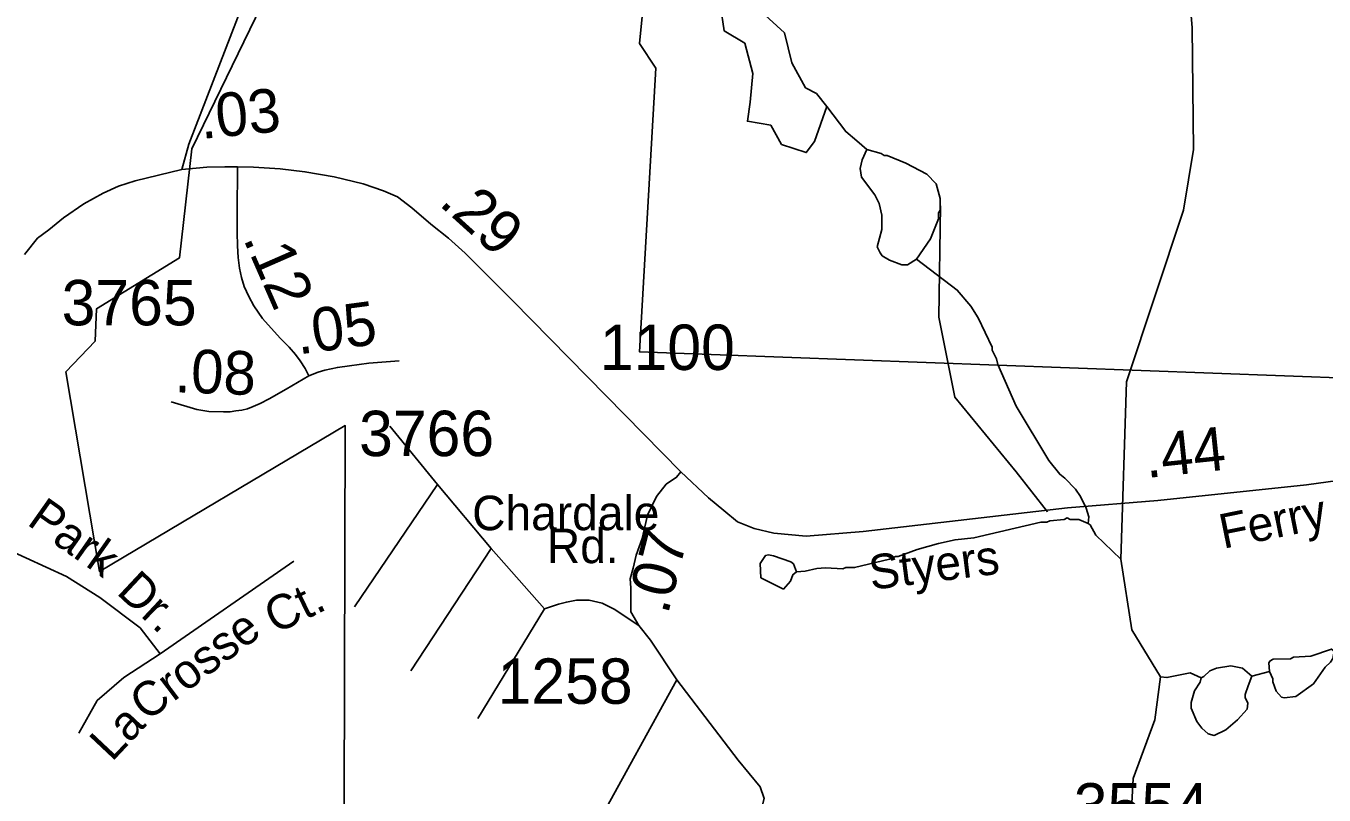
# Model space of a CAD drawing. Extents: x 1547597 to 1699558, y 810033 to 920809.
# Drawn here: x 1584459 to 1588035, y 847300 to 849417 of the extents above; entities that cross this region are included whole.
import ezdxf

# ---------------------------------------------------------------- set-up
doc = ezdxf.new("R2010")
doc.units = 0
for name, color, linetype in [('Exist Boundary Political City Limit New', 7, 'Continuous'), ('Exist Hydrographic Creek Single Shore', 7, 'Continuous'), ('Exist Hydrographic Misc Water Feature', 7, 'Continuous'), ('Exist Road Non-System Type 51', 7, 'Continuous'), ('Exist Road Non-System Type 51 Label', 7, 'Continuous'), ('Exist Road Secondary Mileage Hundredths English Label', 7, 'Continuous'), ('Exist Road Secondary Type 51 Attributed', 7, 'Continuous'), ('Exist Road Secondary Type 51 Label', 7, 'Continuous'), ('Exist Road Secondary Type 51 Number Label', 7, 'Continuous'), ('Map Preparation Boundary City Limit Buffer Line', 7, 'Continuous')]:
    doc.layers.add(name, color=color, linetype=linetype)

msp = doc.modelspace()

# ---------------------------------------------------------------- linework, layer by layer
at = {"layer": 'Exist Boundary Political City Limit New'}
for points in [[(1586285.3, 850744.6), (1585671.5, 851077.7), (1585013.1, 851435.6), (1585004.3, 850606.2), (1585178.8, 849724.5), (1585187.5, 849637.2), (1584916, 849079.1), (1584882.2, 848778.6), (1584653.8, 848638.9), (1584649.6, 848550), (1584569.3, 848465.4), (1584662.3, 847915.1), (1585338.9, 848317.2), (1585331.8, 845895.8)], [(1586285.3, 850744.6), (1586149, 849368.8), (1586194, 849301.3), (1586149, 848520.5), (1589110.2, 848410.1), (1589089.5, 848068.3), (1588960.3, 848086.7), (1588988, 847293), (1589035.6, 846614.1)]]:
    msp.add_lwpolyline(points, dxfattribs=at)
at = {"layer": 'Exist Hydrographic Creek Single Shore'}
msp.add_lwpolyline([(1587450.6, 846262.3), (1587508.6, 847345.1), (1587568.8, 847506.5), (1587584.3, 847624.9), (1587505.5, 847754.8), (1587475.2, 847949.3), (1587490.6, 848437.9), (1587647.5, 848910.7), (1587675.5, 849077.6), (1587671.5, 849412.5), (1587660.6, 849546.6), (1587568.6, 849795.4), (1587582.5, 850146.4), (1587755.6, 850586), (1587750.6, 850835.6), (1587582.5, 851321.6), (1587513.4, 851413.4), (1587235.3, 851702.6), (1587081.6, 851847.2)], dxfattribs=at)
at = {"layer": 'Exist Hydrographic Misc Water Feature'}
msp.add_line((1587884.6, 847639.7), (1587836, 847626.9), dxfattribs=at)
for points in [[(1586372, 849472), (1586382.8, 849403.7), (1586439.2, 849369.8), (1586461.7, 849287), (1586454.2, 849208), (1586446.7, 849155.3), (1586510.6, 849144), (1586540.7, 849091.4), (1586608.4, 849068.8), (1586631, 849098.9), (1586665.6, 849195.5)], [(1586485.6, 849456.6), (1586548.4, 849398.6), (1586568.7, 849315.8), (1586606.4, 849247.5), (1586636.6, 849231.8), (1586665.6, 849195.5), (1586717.5, 849126.6), (1586747.7, 849101.2), (1586775.2, 849077.2)], [(1586775.2, 849077.2), (1586762.8, 849049.3), (1586756.6, 849025.4), (1586760.3, 849001.3), (1586797.7, 848952.9), (1586809.5, 848928.7), (1586817.1, 848896.7), (1586816.6, 848856.7), (1586804.1, 848808.9), (1586811.8, 848792.8), (1586817.7, 848784.8), (1586837.6, 848772.5), (1586871.4, 848760), (1586887.4, 848759.9), (1586912.6, 848775.6)], [(1586912.6, 848775.6), (1586950.3, 848831), (1586972.9, 848886.7), (1586973.1, 848902.7), (1586977.2, 848910.7), (1586977.5, 848942.6), (1586966, 848982.8), (1586940.4, 849009.1), (1586882.8, 849039.8), (1586831, 849060.4), (1586823, 849060.5), (1586815.1, 849066.6), (1586775.2, 849077.2)], [(1586912.6, 848775.6), (1587024.6, 848690.2), (1587062, 848645.7), (1587081.7, 848613.5), (1587120.7, 848533), (1587120.6, 848525.1), (1587132.3, 848500.9), (1587136.1, 848484.9), (1587186.8, 848370.3), (1587276.9, 848221.2), (1587306.5, 848182.9), (1587320.4, 848172.7), (1587350, 848142.3), (1587363.7, 848122.2), (1587379.3, 848090), (1587387.1, 848065.9), (1587384.9, 848047.9)], [(1586581.5, 847914.1), (1586605.5, 847915.8), (1586637.6, 847923.4), (1586661.5, 847925.1), (1586709.5, 847922.5), (1586717.5, 847926.4), (1586741.5, 847926.1), (1586837.8, 847948.9), (1586853.9, 847956.6), (1586861.9, 847956.5), (1586914.2, 847975.9), (1586972.8, 847992.2), (1587018.4, 848002.6), (1587070.4, 848007.9), (1587255, 848051.5), (1587271, 848051.4), (1587279, 848055.3), (1587319, 848058.8), (1587327, 848062.7), (1587335, 848058.6), (1587359, 848058.3), (1587384.9, 848047.9)], [(1587384.9, 848047.9), (1587390.8, 848043.8), (1587406.5, 848015.7), (1587475.2, 847949.3)], [(1586581.5, 847914.1), (1586571.3, 847906.2), (1586565.2, 847888.3), (1586545.5, 847867.1), (1586533, 847872.7), (1586483.6, 847898.2), (1586481.7, 847937.3), (1586496, 847959.2), (1586504.1, 847961.1), (1586518, 847958.9), (1586565.8, 847942.3), (1586573.7, 847936.2), (1586581.5, 847914.1)], [(1587884.6, 847639.7), (1587882.2, 847663.8), (1587886.3, 847669.8), (1587894.3, 847673.7), (1587942.3, 847675.1), (1587950.4, 847679), (1587998.4, 847682.4), (1588054.7, 847701.7), (1588062.6, 847695.6), (1588058.4, 847675.6), (1588052.2, 847665.7), (1588038.1, 847651.9), (1588005.5, 847606.3), (1587957.1, 847570.9), (1587925.1, 847567.4), (1587917.1, 847569.5), (1587903.2, 847585.6), (1587893.6, 847611.7), (1587893.7, 847619.7), (1587884.6, 847639.7)], [(1587696.6, 847622.9), (1587665.9, 847636.6), (1587601.8, 847623.4), (1587584.3, 847624.9)], [(1587696.6, 847622.9), (1587703.8, 847626.1), (1587720, 847641.9), (1587738.1, 847649.6), (1587778.2, 847655.2), (1587810, 847648.8), (1587836, 847626.9)], [(1587836, 847626.9), (1587825.5, 847600.6), (1587817.2, 847576.7), (1587817.1, 847568.7), (1587824.9, 847552.6), (1587822.8, 847536.6), (1587796.4, 847507), (1587764, 847479.4), (1587731.9, 847463.8), (1587715.9, 847468), (1587698.1, 847484.3), (1587684.3, 847502.4), (1587668.8, 847538.6), (1587669, 847554.6), (1587677.4, 847586.4), (1587693.6, 847610.2), (1587696.6, 847622.9)]]:
    msp.add_lwpolyline(points, dxfattribs=at)
at = {"layer": 'Exist Road Non-System Type 51'}
msp.add_line((1586251.8, 847617), (1585516.8, 846285.2), dxfattribs=at)
for points in [[(1586978.7, 848921.8), (1586973.3, 848615.7), (1587018.1, 848395.2), (1587186.9, 848190), (1587273.2, 848079.9)], [(1585593.1, 848155.2), (1585461.6, 848315.7)], [(1585593.1, 848155.2), (1585364.3, 847818.2)], [(1585740.4, 847978.8), (1585593.1, 848155.2)], [(1584121.6, 848123.8), (1584402.9, 847978.3), (1584571.2, 847902), (1584663.2, 847844.1), (1584773.7, 847759.8), (1584828.9, 847688.8)], [(1585740.4, 847978.8), (1585519.5, 847641.9)], [(1585887.9, 847812.1), (1585740.4, 847978.8)], [(1584828.9, 847688.8), (1585197.2, 847944.1)], [(1585887.9, 847812.1), (1585703.6, 847510.3)], [(1585887.9, 847812.1), (1585925.9, 847825.5), (1585948.1, 847831.3), (1585976.2, 847836.7), (1586010.2, 847836.2), (1586046.1, 847827.7), (1586079.9, 847811.2), (1586147.8, 847766.6)], [(1586147.8, 847766.6), (1586179.2, 847726.2), (1586251.8, 847617)], [(1584828.9, 847688.8), (1584729, 847623), (1584655.4, 847559.8), (1584605.4, 847470.3)], [(1586251.8, 847617), (1586421.1, 847395.8), (1586481.6, 847322.1), (1586492.2, 847290.5), (1586421.1, 847006.2)]]:
    msp.add_lwpolyline(points, dxfattribs=at)
at = {"layer": 'Exist Road Secondary Type 51 Attributed'}
for points in [[(1584959.3, 851436), (1584938.1, 851124), (1584924.8, 850935.9), (1584921.9, 850850.4), (1584921, 850761.9), (1584923.9, 850698.8), (1584930.4, 850636.3), (1584937.8, 850582), (1584966.4, 850437.6), (1585039.8, 850106.1), (1585061.9, 849997), (1585100, 849833.6), (1585114.4, 849755.8), (1585118.6, 849710.4), (1585116.8, 849682.7), (1585112.1, 849648.5), (1585100.9, 849598.3), (1585042.2, 849439.1), (1584908, 849091.7), (1584888.6, 849022.1)], [(1584888.6, 849022.1), (1584957.9, 849028.3), (1585006.9, 849029.8), (1585042.2, 849029.3)], [(1585042.2, 849029.3), (1585040.9, 848903.3), (1585040.8, 848848.6), (1585041.7, 848812.1), (1585044.3, 848780), (1585047.8, 848750.5), (1585053, 848725.3), (1585060.8, 848700.2), (1585072.9, 848672.4), (1585086.8, 848647.2), (1585111.2, 848611.6), (1585159.8, 848557.8), (1585184.1, 848532.6), (1585201.5, 848512.7), (1585214.5, 848495.3), (1585228.4, 848474.5), (1585238.8, 848454.5)], [(1585042.2, 849029.3), (1585085.7, 849028.8), (1585160, 849023.7), (1585227.9, 849016), (1585308.6, 849001.9), (1585388, 848982.7), (1585444.4, 848963.5), (1585482.8, 848946.9), (1585522.5, 848916.4), (1585574.9, 848871.9), (1585623.3, 848833.2), (1585669.2, 848791.7), (1585800.6, 848660.2), (1586263, 848189.6)], [(1584455.7, 848788.6), (1584490.9, 848832.8), (1584522.3, 848856.4), (1584563, 848888.8), (1584618.4, 848927.8), (1584671.7, 848957.1), (1584714, 848976.1), (1584760.4, 848991.5), (1584888.6, 849022.1)], [(1585486.9, 848495.3), (1585404.2, 848488.6), (1585350.6, 848481.9), (1585317.1, 848477.5), (1585282.9, 848470), (1585264.3, 848464.1), (1585238.8, 848454.5)], [(1585238.8, 848454.5), (1585175.7, 848417.2), (1585129.5, 848390.4), (1585104.9, 848377.7), (1585084.8, 848369.6), (1585069.2, 848363.6), (1585054.3, 848359.9), (1585037.9, 848357.7), (1585021.6, 848355.4), (1585003.7, 848354.7), (1584963.5, 848356.2), (1584930, 848361.4), (1584859.2, 848382.2)], [(1586263, 848189.6), (1586339.6, 848118.6), (1586381.4, 848082.9), (1586419.6, 848051.8), (1586465.3, 848033.7), (1586519, 848021), (1586608.6, 848012.3), (1586765, 848025.1), (1587328.1, 848090.2), (1587577.1, 848111), (1587986.5, 848154), (1588152.7, 848176.7), (1588248.2, 848186.1), (1588327.7, 848208.6), (1588367.4, 848225.9), (1588415.7, 848246.6), (1588460.6, 848270.8)], [(1586263, 848189.6), (1586251.2, 848175), (1586222.9, 848155.4), (1586196.2, 848122), (1586171.7, 848070.9), (1586156.2, 848006.3), (1586140, 847960.4), (1586131.4, 847924.3), (1586124, 847894.7), (1586125.7, 847870.7), (1586125, 847843.9), (1586125, 847803.9), (1586147.8, 847766.6)]]:
    msp.add_lwpolyline(points, dxfattribs=at)
at = {"layer": 'Map Preparation Boundary City Limit Buffer Line'}
for points in [[(1586285.3, 850744.6), (1585671.5, 851077.7), (1585013.1, 851435.6), (1585004.3, 850606.2), (1585178.8, 849724.5), (1585187.5, 849637.2), (1584916, 849079.1), (1584882.2, 848778.6), (1584653.8, 848638.9), (1584649.6, 848550), (1584569.3, 848465.4), (1584662.3, 847915.1), (1585338.9, 848317.2), (1585331.8, 845895.8)], [(1586285.3, 850744.6), (1586149, 849368.8), (1586194, 849301.3), (1586149, 848520.5), (1589110.2, 848410.1), (1589089.5, 848068.3), (1588960.3, 848086.7), (1588988, 847293), (1589035.6, 846614.1)]]:
    msp.add_lwpolyline(points, dxfattribs=at)

# ---------------------------------------------------------------- texts
at = {"layer": 'Exist Road Non-System Type 51 Label'}
for s, rotation, p in [('Park', 324.7995, (1584459.2, 848046.3)), ('Dr.', 316.84, (1584706.1, 847855.8)), ('Ct.', 25.7042, (1585145.9, 847742.1)), ('Crosse', 37.0455, (1584791.8, 847500)), ('La', 46.7578, (1584696, 847389.2))]:
    msp.add_text(s, height=95, rotation=rotation, dxfattribs=at).set_placement(p)
at = {"layer": 'Exist Road Secondary Mileage Hundredths English Label'}
for s, rotation, p in [('.03', 5.6367, (1584943.2, 849106.2)), ('.29', 317.8867, (1585593.9, 848926.1)), ('.12', 293.6413, (1585056.8, 848832)), ('.05', 7.5898, (1585209.9, 848512.8)), ('.08', 357.8806, (1584867.9, 848409)), ('.44', 6.0221, (1587546.3, 848172.6)), ('.07', 75.5587, (1586227.1, 847794.3))]:
    msp.add_text(s, height=120, rotation=rotation, dxfattribs=at).set_placement(p)
at = {"layer": 'Exist Road Secondary Type 51 Label'}
for s, p in [('Chardale', (1585688.4, 848029.1)), ('Rd.', (1585894.3, 847938.3))]:
    msp.add_text(s, height=95, dxfattribs=at).set_placement(p)
for s, rotation, p in [('Ferry', 11.5007, (1587756.9, 847977.7)), ('Styers', 7.2271, (1586787.4, 847864.6))]:
    msp.add_text(s, height=95, rotation=rotation, dxfattribs=at).set_placement(p)
at = {"layer": 'Exist Road Secondary Type 51 Number Label'}
for s, p in [('3765', (1584557.7, 848593.1)), ('1100', (1586040, 848470.3)), ('3766', (1585377, 848233)), ('1258', (1585758.4, 847551)), ('3554', (1587345.3, 847207.5))]:
    msp.add_text(s, height=125, dxfattribs=at).set_placement(p)

doc.saveas('drawing.dxf')
